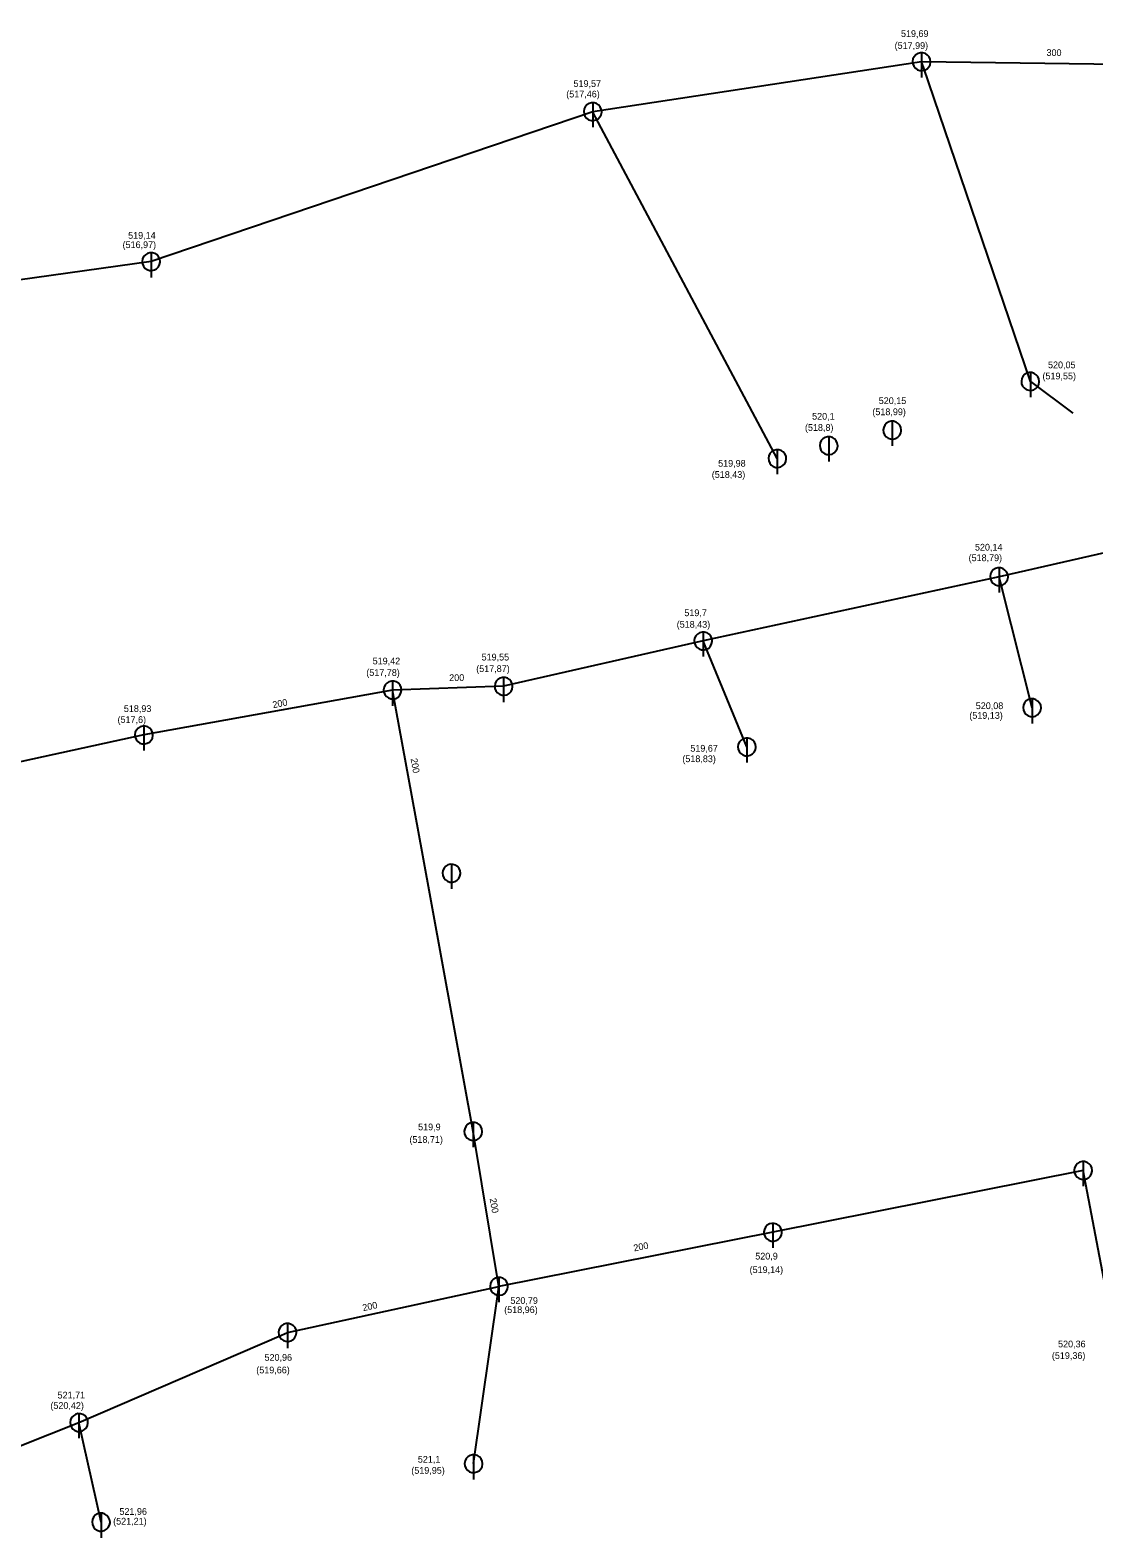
# Model space of a CAD drawing. Extents: x -476058 to -471893, y -1155786 to -1152000.
# Drawn here: x -473883.9 to -473765.3, y -1154048.8 to -1153880.8 of the extents above; entities that cross this region are included whole.
import ezdxf

# ---------------------------------------------------------------- set-up
doc = ezdxf.new("R2010")
doc.units = 0
for name, color, linetype in [('Vrstva 10', 7, 'Continuous'), ('Vrstva 18', 7, 'Continuous'), ('Vrstva 3', 7, 'Continuous'), ('Vrstva 4', 7, 'Continuous'), ('Vrstva 45', 7, 'Continuous'), ('Vrstva 50', 7, 'Continuous'), ('Vrstva 51', 7, 'Continuous')]:
    doc.layers.add(name, color=color, linetype=linetype)

msp = doc.modelspace()

# ---------------------------------------------------------------- linework, layer by layer
at = {"layer": 'Vrstva 10'}
for p, q in [((-473784.49, -1153883.3), (-473784.49, -1153886.05)), ((-473821.17, -1153888.87), (-473821.17, -1153891.61)), ((-473870.42, -1153905.58), (-473870.42, -1153908.33)), ((-473772.36, -1153918.93), (-473772.36, -1153921.68)), ((-473787.76, -1153924.36), (-473787.76, -1153927.11)), ((-473794.85, -1153926.09), (-473794.85, -1153928.84)), ((-473800.58, -1153927.53), (-473800.58, -1153930.28)), ((-473775.85, -1153940.7), (-473775.85, -1153943.45)), ((-473808.85, -1153947.85), (-473808.85, -1153950.6)), ((-473843.49, -1153953.32), (-473843.49, -1153956.07)), ((-473831.1, -1153952.91), (-473831.1, -1153955.66)), ((-473772.17, -1153955.3), (-473772.17, -1153958.05)), ((-473871.23, -1153958.33), (-473871.23, -1153961.08)), ((-473803.98, -1153959.67), (-473803.98, -1153962.41)), ((-473836.92, -1153973.74), (-473836.92, -1153976.48)), ((-473834.49, -1154002.52), (-473834.49, -1154005.26)), ((-473766.47, -1154006.87), (-473766.47, -1154009.62)), ((-473801.07, -1154013.75), (-473801.07, -1154016.5)), ((-473831.62, -1154019.78), (-473831.62, -1154022.53)), ((-473855.21, -1154024.92), (-473855.21, -1154027.67)), ((-473878.46, -1154034.96), (-473878.46, -1154037.71)), ((-473834.46, -1154039.54), (-473834.46, -1154042.29)), ((-473876, -1154046.06), (-473876, -1154048.81))]:
    msp.add_line(p, q, dxfattribs=at)
for points in [[(-473783.49, -1153884.3), (-473783.53, -1153884.02), (-473783.65, -1153883.76), (-473783.83, -1153883.55), (-473784.07, -1153883.39), (-473784.34, -1153883.31), (-473784.62, -1153883.31), (-473784.89, -1153883.38), (-473785.13, -1153883.53), (-473785.32, -1153883.74), (-473785.45, -1153883.99), (-473785.49, -1153884.27), (-473785.46, -1153884.55), (-473785.35, -1153884.81), (-473785.17, -1153885.03), (-473784.94, -1153885.19), (-473784.68, -1153885.28), (-473784.39, -1153885.29), (-473784.12, -1153885.23), (-473783.88, -1153885.09), (-473783.68, -1153884.88), (-473783.55, -1153884.63), (-473783.49, -1153884.35), (-473783.49, -1153884.3)], [(-473820.17, -1153889.87), (-473820.21, -1153889.59), (-473820.33, -1153889.33), (-473820.51, -1153889.12), (-473820.75, -1153888.96), (-473821.02, -1153888.88), (-473821.3, -1153888.88), (-473821.57, -1153888.95), (-473821.81, -1153889.1), (-473822, -1153889.31), (-473822.12, -1153889.56), (-473822.17, -1153889.84), (-473822.14, -1153890.12), (-473822.03, -1153890.38), (-473821.85, -1153890.6), (-473821.62, -1153890.76), (-473821.35, -1153890.85), (-473821.07, -1153890.86), (-473820.8, -1153890.79), (-473820.55, -1153890.65), (-473820.36, -1153890.45), (-473820.23, -1153890.2), (-473820.17, -1153889.92), (-473820.17, -1153889.87)], [(-473869.42, -1153906.58), (-473869.46, -1153906.3), (-473869.58, -1153906.04), (-473869.76, -1153905.83), (-473869.99, -1153905.68), (-473870.27, -1153905.59), (-473870.55, -1153905.59), (-473870.82, -1153905.66), (-473871.06, -1153905.81), (-473871.25, -1153906.02), (-473871.37, -1153906.27), (-473871.42, -1153906.55), (-473871.39, -1153906.83), (-473871.28, -1153907.09), (-473871.1, -1153907.31), (-473870.87, -1153907.47), (-473870.6, -1153907.56), (-473870.32, -1153907.58), (-473870.05, -1153907.51), (-473869.8, -1153907.37), (-473869.61, -1153907.16), (-473869.48, -1153906.91), (-473869.42, -1153906.64), (-473869.42, -1153906.58)], [(-473771.36, -1153919.93), (-473771.4, -1153919.65), (-473771.51, -1153919.39), (-473771.7, -1153919.18), (-473771.93, -1153919.03), (-473772.2, -1153918.94), (-473772.48, -1153918.94), (-473772.76, -1153919.01), (-473773, -1153919.16), (-473773.19, -1153919.37), (-473773.31, -1153919.62), (-473773.36, -1153919.9), (-473773.33, -1153920.18), (-473773.22, -1153920.44), (-473773.04, -1153920.66), (-473772.81, -1153920.82), (-473772.54, -1153920.91), (-473772.26, -1153920.93), (-473771.98, -1153920.86), (-473771.74, -1153920.72), (-473771.54, -1153920.51), (-473771.42, -1153920.26), (-473771.36, -1153919.99), (-473771.36, -1153919.93)], [(-473786.76, -1153925.36), (-473786.8, -1153925.08), (-473786.92, -1153924.82), (-473787.1, -1153924.61), (-473787.34, -1153924.46), (-473787.61, -1153924.37), (-473787.89, -1153924.37), (-473788.16, -1153924.44), (-473788.4, -1153924.59), (-473788.59, -1153924.8), (-473788.71, -1153925.05), (-473788.76, -1153925.33), (-473788.73, -1153925.61), (-473788.62, -1153925.87), (-473788.44, -1153926.09), (-473788.21, -1153926.26), (-473787.94, -1153926.34), (-473787.66, -1153926.36), (-473787.39, -1153926.29), (-473787.14, -1153926.15), (-473786.95, -1153925.94), (-473786.82, -1153925.69), (-473786.76, -1153925.42), (-473786.76, -1153925.36)], [(-473793.85, -1153927.09), (-473793.89, -1153926.81), (-473794.01, -1153926.56), (-473794.19, -1153926.34), (-473794.43, -1153926.19), (-473794.7, -1153926.1), (-473794.98, -1153926.1), (-473795.25, -1153926.18), (-473795.49, -1153926.32), (-473795.68, -1153926.53), (-473795.8, -1153926.79), (-473795.85, -1153927.06), (-473795.82, -1153927.34), (-473795.71, -1153927.6), (-473795.53, -1153927.82), (-473795.3, -1153927.99), (-473795.04, -1153928.08), (-473794.75, -1153928.09), (-473794.48, -1153928.02), (-473794.23, -1153927.88), (-473794.04, -1153927.68), (-473793.91, -1153927.43), (-473793.85, -1153927.15), (-473793.85, -1153927.09)], [(-473799.58, -1153928.53), (-473799.61, -1153928.25), (-473799.73, -1153927.99), (-473799.92, -1153927.78), (-473800.15, -1153927.62), (-473800.42, -1153927.54), (-473800.7, -1153927.54), (-473800.98, -1153927.61), (-473801.22, -1153927.76), (-473801.41, -1153927.97), (-473801.53, -1153928.22), (-473801.58, -1153928.5), (-473801.54, -1153928.78), (-473801.43, -1153929.04), (-473801.26, -1153929.26), (-473801.03, -1153929.42), (-473800.76, -1153929.51), (-473800.48, -1153929.52), (-473800.2, -1153929.46), (-473799.96, -1153929.31), (-473799.76, -1153929.11), (-473799.63, -1153928.86), (-473799.58, -1153928.58), (-473799.58, -1153928.53)], [(-473774.85, -1153941.7), (-473774.89, -1153941.42), (-473775.01, -1153941.16), (-473775.19, -1153940.95), (-473775.42, -1153940.79), (-473775.7, -1153940.71), (-473775.98, -1153940.71), (-473776.25, -1153940.78), (-473776.49, -1153940.93), (-473776.68, -1153941.14), (-473776.8, -1153941.39), (-473776.85, -1153941.67), (-473776.82, -1153941.95), (-473776.71, -1153942.21), (-473776.53, -1153942.43), (-473776.3, -1153942.59), (-473776.03, -1153942.68), (-473775.75, -1153942.7), (-473775.48, -1153942.63), (-473775.23, -1153942.49), (-473775.04, -1153942.28), (-473774.91, -1153942.03), (-473774.85, -1153941.76), (-473774.85, -1153941.7)], [(-473807.85, -1153948.85), (-473807.89, -1153948.57), (-473808, -1153948.31), (-473808.19, -1153948.1), (-473808.42, -1153947.95), (-473808.69, -1153947.86), (-473808.98, -1153947.86), (-473809.25, -1153947.93), (-473809.49, -1153948.08), (-473809.68, -1153948.29), (-473809.8, -1153948.54), (-473809.85, -1153948.82), (-473809.82, -1153949.1), (-473809.71, -1153949.36), (-473809.53, -1153949.58), (-473809.3, -1153949.74), (-473809.03, -1153949.83), (-473808.75, -1153949.85), (-473808.47, -1153949.78), (-473808.23, -1153949.64), (-473808.04, -1153949.43), (-473807.91, -1153949.18), (-473807.85, -1153948.91), (-473807.85, -1153948.85)], [(-473842.49, -1153954.32), (-473842.53, -1153954.04), (-473842.65, -1153953.78), (-473842.83, -1153953.57), (-473843.07, -1153953.42), (-473843.34, -1153953.33), (-473843.62, -1153953.33), (-473843.89, -1153953.4), (-473844.13, -1153953.55), (-473844.32, -1153953.76), (-473844.44, -1153954.01), (-473844.49, -1153954.29), (-473844.46, -1153954.57), (-473844.35, -1153954.83), (-473844.17, -1153955.05), (-473843.94, -1153955.21), (-473843.67, -1153955.3), (-473843.39, -1153955.32), (-473843.12, -1153955.25), (-473842.87, -1153955.11), (-473842.68, -1153954.9), (-473842.55, -1153954.65), (-473842.49, -1153954.38), (-473842.49, -1153954.32)], [(-473830.1, -1153953.91), (-473830.14, -1153953.63), (-473830.25, -1153953.37), (-473830.44, -1153953.16), (-473830.67, -1153953), (-473830.94, -1153952.92), (-473831.22, -1153952.92), (-473831.5, -1153952.99), (-473831.74, -1153953.14), (-473831.93, -1153953.35), (-473832.05, -1153953.6), (-473832.1, -1153953.88), (-473832.07, -1153954.16), (-473831.96, -1153954.42), (-473831.78, -1153954.64), (-473831.55, -1153954.8), (-473831.28, -1153954.89), (-473831, -1153954.91), (-473830.72, -1153954.84), (-473830.48, -1153954.7), (-473830.28, -1153954.49), (-473830.15, -1153954.24), (-473830.1, -1153953.97), (-473830.1, -1153953.91)], [(-473771.17, -1153956.3), (-473771.21, -1153956.02), (-473771.33, -1153955.77), (-473771.51, -1153955.55), (-473771.75, -1153955.4), (-473772.02, -1153955.31), (-473772.3, -1153955.31), (-473772.57, -1153955.38), (-473772.81, -1153955.53), (-473773, -1153955.74), (-473773.12, -1153956), (-473773.17, -1153956.27), (-473773.14, -1153956.55), (-473773.03, -1153956.81), (-473772.85, -1153957.03), (-473772.62, -1153957.2), (-473772.35, -1153957.28), (-473772.07, -1153957.3), (-473771.8, -1153957.23), (-473771.55, -1153957.09), (-473771.36, -1153956.88), (-473771.23, -1153956.63), (-473771.17, -1153956.36), (-473771.17, -1153956.3)], [(-473870.23, -1153959.33), (-473870.27, -1153959.06), (-473870.38, -1153958.8), (-473870.57, -1153958.58), (-473870.8, -1153958.43), (-473871.07, -1153958.35), (-473871.35, -1153958.34), (-473871.62, -1153958.42), (-473871.86, -1153958.57), (-473872.05, -1153958.78), (-473872.18, -1153959.03), (-473872.23, -1153959.31), (-473872.19, -1153959.59), (-473872.09, -1153959.85), (-473871.91, -1153960.07), (-473871.68, -1153960.23), (-473871.41, -1153960.32), (-473871.13, -1153960.33), (-473870.85, -1153960.26), (-473870.61, -1153960.12), (-473870.41, -1153959.92), (-473870.28, -1153959.67), (-473870.23, -1153959.39), (-473870.23, -1153959.33)], [(-473802.98, -1153960.67), (-473803.02, -1153960.39), (-473803.13, -1153960.13), (-473803.32, -1153959.91), (-473803.55, -1153959.76), (-473803.82, -1153959.68), (-473804.1, -1153959.67), (-473804.38, -1153959.75), (-473804.62, -1153959.9), (-473804.81, -1153960.1), (-473804.93, -1153960.36), (-473804.98, -1153960.64), (-473804.95, -1153960.92), (-473804.84, -1153961.18), (-473804.66, -1153961.4), (-473804.43, -1153961.56), (-473804.16, -1153961.65), (-473803.88, -1153961.66), (-473803.6, -1153961.59), (-473803.36, -1153961.45), (-473803.16, -1153961.25), (-473803.03, -1153961), (-473802.98, -1153960.72), (-473802.98, -1153960.67)], [(-473835.92, -1153974.74), (-473835.96, -1153974.46), (-473836.07, -1153974.2), (-473836.26, -1153973.98), (-473836.49, -1153973.83), (-473836.76, -1153973.75), (-473837.04, -1153973.74), (-473837.32, -1153973.82), (-473837.55, -1153973.97), (-473837.74, -1153974.18), (-473837.87, -1153974.43), (-473837.92, -1153974.71), (-473837.88, -1153974.99), (-473837.78, -1153975.25), (-473837.6, -1153975.47), (-473837.37, -1153975.63), (-473837.1, -1153975.72), (-473836.82, -1153975.73), (-473836.54, -1153975.66), (-473836.3, -1153975.52), (-473836.1, -1153975.32), (-473835.97, -1153975.07), (-473835.92, -1153974.79), (-473835.92, -1153974.74)], [(-473833.49, -1154003.52), (-473833.53, -1154003.24), (-473833.65, -1154002.98), (-473833.83, -1154002.76), (-473834.06, -1154002.61), (-473834.33, -1154002.53), (-473834.62, -1154002.52), (-473834.89, -1154002.6), (-473835.13, -1154002.75), (-473835.32, -1154002.96), (-473835.44, -1154003.21), (-473835.49, -1154003.49), (-473835.46, -1154003.77), (-473835.35, -1154004.03), (-473835.17, -1154004.25), (-473834.94, -1154004.41), (-473834.67, -1154004.5), (-473834.39, -1154004.51), (-473834.11, -1154004.44), (-473833.87, -1154004.3), (-473833.68, -1154004.1), (-473833.55, -1154003.85), (-473833.49, -1154003.57), (-473833.49, -1154003.52)], [(-473765.47, -1154007.87), (-473765.51, -1154007.59), (-473765.63, -1154007.33), (-473765.81, -1154007.12), (-473766.04, -1154006.97), (-473766.32, -1154006.88), (-473766.6, -1154006.88), (-473766.87, -1154006.95), (-473767.11, -1154007.1), (-473767.3, -1154007.31), (-473767.42, -1154007.56), (-473767.47, -1154007.84), (-473767.44, -1154008.12), (-473767.33, -1154008.38), (-473767.15, -1154008.6), (-473766.92, -1154008.76), (-473766.65, -1154008.85), (-473766.37, -1154008.87), (-473766.1, -1154008.8), (-473765.85, -1154008.66), (-473765.66, -1154008.45), (-473765.53, -1154008.2), (-473765.47, -1154007.93), (-473765.47, -1154007.87)], [(-473800.07, -1154014.75), (-473800.11, -1154014.47), (-473800.23, -1154014.21), (-473800.41, -1154014), (-473800.65, -1154013.84), (-473800.92, -1154013.76), (-473801.2, -1154013.76), (-473801.47, -1154013.83), (-473801.71, -1154013.98), (-473801.9, -1154014.19), (-473802.02, -1154014.44), (-473802.07, -1154014.72), (-473802.04, -1154015), (-473801.93, -1154015.26), (-473801.75, -1154015.48), (-473801.52, -1154015.64), (-473801.25, -1154015.73), (-473800.97, -1154015.75), (-473800.7, -1154015.68), (-473800.45, -1154015.54), (-473800.26, -1154015.33), (-473800.13, -1154015.08), (-473800.07, -1154014.81), (-473800.07, -1154014.75)], [(-473830.62, -1154020.78), (-473830.66, -1154020.5), (-473830.78, -1154020.24), (-473830.96, -1154020.03), (-473831.2, -1154019.88), (-473831.47, -1154019.79), (-473831.75, -1154019.79), (-473832.02, -1154019.86), (-473832.26, -1154020.01), (-473832.45, -1154020.22), (-473832.57, -1154020.47), (-473832.62, -1154020.75), (-473832.59, -1154021.03), (-473832.48, -1154021.29), (-473832.3, -1154021.51), (-473832.07, -1154021.67), (-473831.8, -1154021.76), (-473831.52, -1154021.78), (-473831.25, -1154021.71), (-473831, -1154021.57), (-473830.81, -1154021.36), (-473830.68, -1154021.11), (-473830.62, -1154020.84), (-473830.62, -1154020.78)], [(-473854.21, -1154025.92), (-473854.25, -1154025.64), (-473854.37, -1154025.38), (-473854.55, -1154025.17), (-473854.79, -1154025.02), (-473855.05, -1154024.93), (-473855.34, -1154024.93), (-473855.61, -1154025), (-473855.85, -1154025.15), (-473856.04, -1154025.36), (-473856.16, -1154025.61), (-473856.21, -1154025.89), (-473856.18, -1154026.17), (-473856.07, -1154026.43), (-473855.89, -1154026.65), (-473855.66, -1154026.81), (-473855.39, -1154026.9), (-473855.11, -1154026.92), (-473854.84, -1154026.85), (-473854.59, -1154026.71), (-473854.4, -1154026.5), (-473854.27, -1154026.25), (-473854.21, -1154025.98), (-473854.21, -1154025.92)], [(-473877.46, -1154035.96), (-473877.49, -1154035.69), (-473877.61, -1154035.43), (-473877.79, -1154035.21), (-473878.03, -1154035.06), (-473878.3, -1154034.98), (-473878.58, -1154034.97), (-473878.85, -1154035.05), (-473879.09, -1154035.2), (-473879.28, -1154035.4), (-473879.41, -1154035.66), (-473879.46, -1154035.94), (-473879.42, -1154036.22), (-473879.31, -1154036.48), (-473879.14, -1154036.7), (-473878.91, -1154036.86), (-473878.64, -1154036.95), (-473878.35, -1154036.96), (-473878.08, -1154036.89), (-473877.84, -1154036.75), (-473877.64, -1154036.55), (-473877.51, -1154036.3), (-473877.46, -1154036.02), (-473877.46, -1154035.96)], [(-473833.46, -1154040.54), (-473833.49, -1154040.26), (-473833.61, -1154040.01), (-473833.79, -1154039.79), (-473834.03, -1154039.64), (-473834.3, -1154039.55), (-473834.58, -1154039.55), (-473834.85, -1154039.63), (-473835.1, -1154039.77), (-473835.29, -1154039.98), (-473835.41, -1154040.24), (-473835.46, -1154040.52), (-473835.42, -1154040.8), (-473835.32, -1154041.06), (-473835.14, -1154041.28), (-473834.91, -1154041.44), (-473834.64, -1154041.53), (-473834.36, -1154041.54), (-473834.08, -1154041.47), (-473833.84, -1154041.33), (-473833.64, -1154041.13), (-473833.51, -1154040.88), (-473833.46, -1154040.6), (-473833.46, -1154040.54)], [(-473875, -1154047.06), (-473875.04, -1154046.78), (-473875.16, -1154046.53), (-473875.34, -1154046.31), (-473875.58, -1154046.16), (-473875.85, -1154046.07), (-473876.13, -1154046.07), (-473876.4, -1154046.15), (-473876.64, -1154046.29), (-473876.83, -1154046.5), (-473876.95, -1154046.76), (-473877, -1154047.03), (-473876.97, -1154047.31), (-473876.86, -1154047.57), (-473876.68, -1154047.79), (-473876.45, -1154047.96), (-473876.18, -1154048.05), (-473875.9, -1154048.06), (-473875.63, -1154047.99), (-473875.38, -1154047.85), (-473875.19, -1154047.65), (-473875.06, -1154047.4), (-473875, -1154047.12), (-473875, -1154047.06)]]:
    msp.add_lwpolyline(points, dxfattribs=at)
at = {"layer": 'Vrstva 45'}
for points in [[(-473784.49, -1153884.3), (-473821.17, -1153889.87)], [(-473754.28, -1153884.71), (-473784.49, -1153884.3)], [(-473821.17, -1153889.87), (-473870.42, -1153906.58)], [(-473870.42, -1153906.58), (-473937.11, -1153915.89)], [(-473752.67, -1153936.43), (-473775.85, -1153941.7)], [(-473775.85, -1153941.7), (-473808.85, -1153948.85)], [(-473808.85, -1153948.85), (-473831.1, -1153953.91)], [(-473843.49, -1153954.32), (-473871.23, -1153959.33)], [(-473831.1, -1153953.91), (-473843.49, -1153954.32)], [(-473840.19, -1153972.35), (-473843.49, -1153954.32)], [(-473871.23, -1153959.33), (-473896.09, -1153964.74)], [(-473834.49, -1154003.52), (-473840.19, -1153972.35)], [(-473831.62, -1154020.78), (-473834.49, -1154003.52)], [(-473766.47, -1154007.87), (-473801.07, -1154014.75)], [(-473762.78, -1154027.14), (-473766.47, -1154007.87)], [(-473801.07, -1154014.75), (-473831.62, -1154020.78)], [(-473855.21, -1154025.92), (-473831.62, -1154020.78)]]:
    msp.add_lwpolyline(points, dxfattribs=at)
at = {"layer": 'Vrstva 50'}
for points in [[(-473784.28, -1153884.92), (-473784.49, -1153884.3)], [(-473772.36, -1153919.93), (-473784.28, -1153884.92)], [(-473820.85, -1153890.48), (-473821.17, -1153889.87)], [(-473800.58, -1153928.53), (-473820.85, -1153890.48)], [(-473772.17, -1153956.3), (-473775.69, -1153942.32), (-473775.85, -1153941.7)], [(-473803.98, -1153960.67), (-473808.62, -1153949.41), (-473808.85, -1153948.85)], [(-473834.46, -1154040.54), (-473831.71, -1154021.4), (-473831.62, -1154020.78)], [(-473855.89, -1154026.21), (-473855.21, -1154025.92)], [(-473878.46, -1154035.96), (-473855.89, -1154026.21)], [(-473905.25, -1154046.58), (-473878.46, -1154035.96)], [(-473876, -1154047.06), (-473878.46, -1154035.96)]]:
    msp.add_lwpolyline(points, dxfattribs=at)
at = {"layer": 'Vrstva 51'}
msp.add_lwpolyline([(-473772.36, -1153919.93), (-473767.63, -1153923.46)], dxfattribs=at)

# ---------------------------------------------------------------- texts
at = {"layer": 'Vrstva 18'}
for s, rotation, p in [('300 ', 359.2283, (-473770.56, -1153883.65)), ('200 ', 0.4771, (-473837.17, -1153953.32)), ('200 ', 11.2049, (-473856.8, -1153956.35)), ('200 ', 280.1254, (-473841.48, -1153961.99)), ('200 ', 280.1271, (-473832.67, -1154011.02)), ('200 ', 11.1656, (-473816.54, -1154016.89)), ('200 ', 12.292, (-473846.76, -1154023.55))]:
    msp.add_text(s, height=0.75, rotation=rotation, dxfattribs=at).set_placement(p)
at = {"layer": 'Vrstva 3'}
for s, p in [('519,69', (-473786.79, -1153881.54)), ('519,57', (-473823.31, -1153887.11)), ('519,14', (-473872.98, -1153904.03)), ('520,05', (-473770.39, -1153918.46)), ('520,15', (-473789.27, -1153922.45)), ('520,1', (-473796.7, -1153924.19)), ('519,98', (-473807.18, -1153929.43)), ('520,14', (-473778.54, -1153938.78)), ('519,7', (-473810.95, -1153946.09)), ('519,55', (-473833.56, -1153951.03)), ('519,42', (-473845.71, -1153951.46)), ('518,93', (-473873.46, -1153956.77)), ('520,08', (-473778.45, -1153956.45)), ('519,67', (-473810.28, -1153961.19)), ('519,9', (-473840.64, -1154003.39)), ('520,9', (-473803.04, -1154017.79)), ('520,79', (-473830.35, -1154022.74)), ('520,36', (-473769.27, -1154027.58)), ('520,96', (-473857.77, -1154029.08)), ('521,71', (-473880.85, -1154033.28)), ('521,1', (-473840.67, -1154040.43)), ('521,96', (-473873.95, -1154046.25))]:
    msp.add_text(s, height=0.75, dxfattribs=at).set_placement(p)
at = {"layer": 'Vrstva 4'}
for s, p in [('(517,99)', (-473787.5, -1153882.87)), ('(517,46)', (-473824.12, -1153888.28)), ('(516,97)', (-473873.6, -1153905.07)), ('(519,55)', (-473771.01, -1153919.7)), ('(518,99)', (-473789.98, -1153923.69)), ('(518,8)', (-473797.5, -1153925.44)), ('(518,43)', (-473807.89, -1153930.68)), ('(518,79)', (-473779.25, -1153939.96)), ('(518,43)', (-473811.8, -1153947.38)), ('(517,78)', (-473846.42, -1153952.75)), ('(517,87)', (-473834.16, -1153952.32)), ('(519,13)', (-473779.17, -1153957.53)), ('(517,6)', (-473874.16, -1153957.99)), ('(518,83)', (-473811.17, -1153962.36)), ('(518,71)', (-473841.61, -1154004.79)), ('(519,14)', (-473803.67, -1154019.3)), ('(518,96)', (-473831.04, -1154023.76)), ('(519,36)', (-473769.96, -1154028.87)), ('(519,66)', (-473858.69, -1154030.48)), ('(520,42)', (-473881.65, -1154034.44)), ('(519,95)', (-473841.4, -1154041.67)), ('(521,21)', (-473874.65, -1154047.33))]:
    msp.add_text(s, height=0.75, dxfattribs=at).set_placement(p)

doc.saveas('drawing.dxf')
